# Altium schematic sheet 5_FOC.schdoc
size 431 x 309 mm
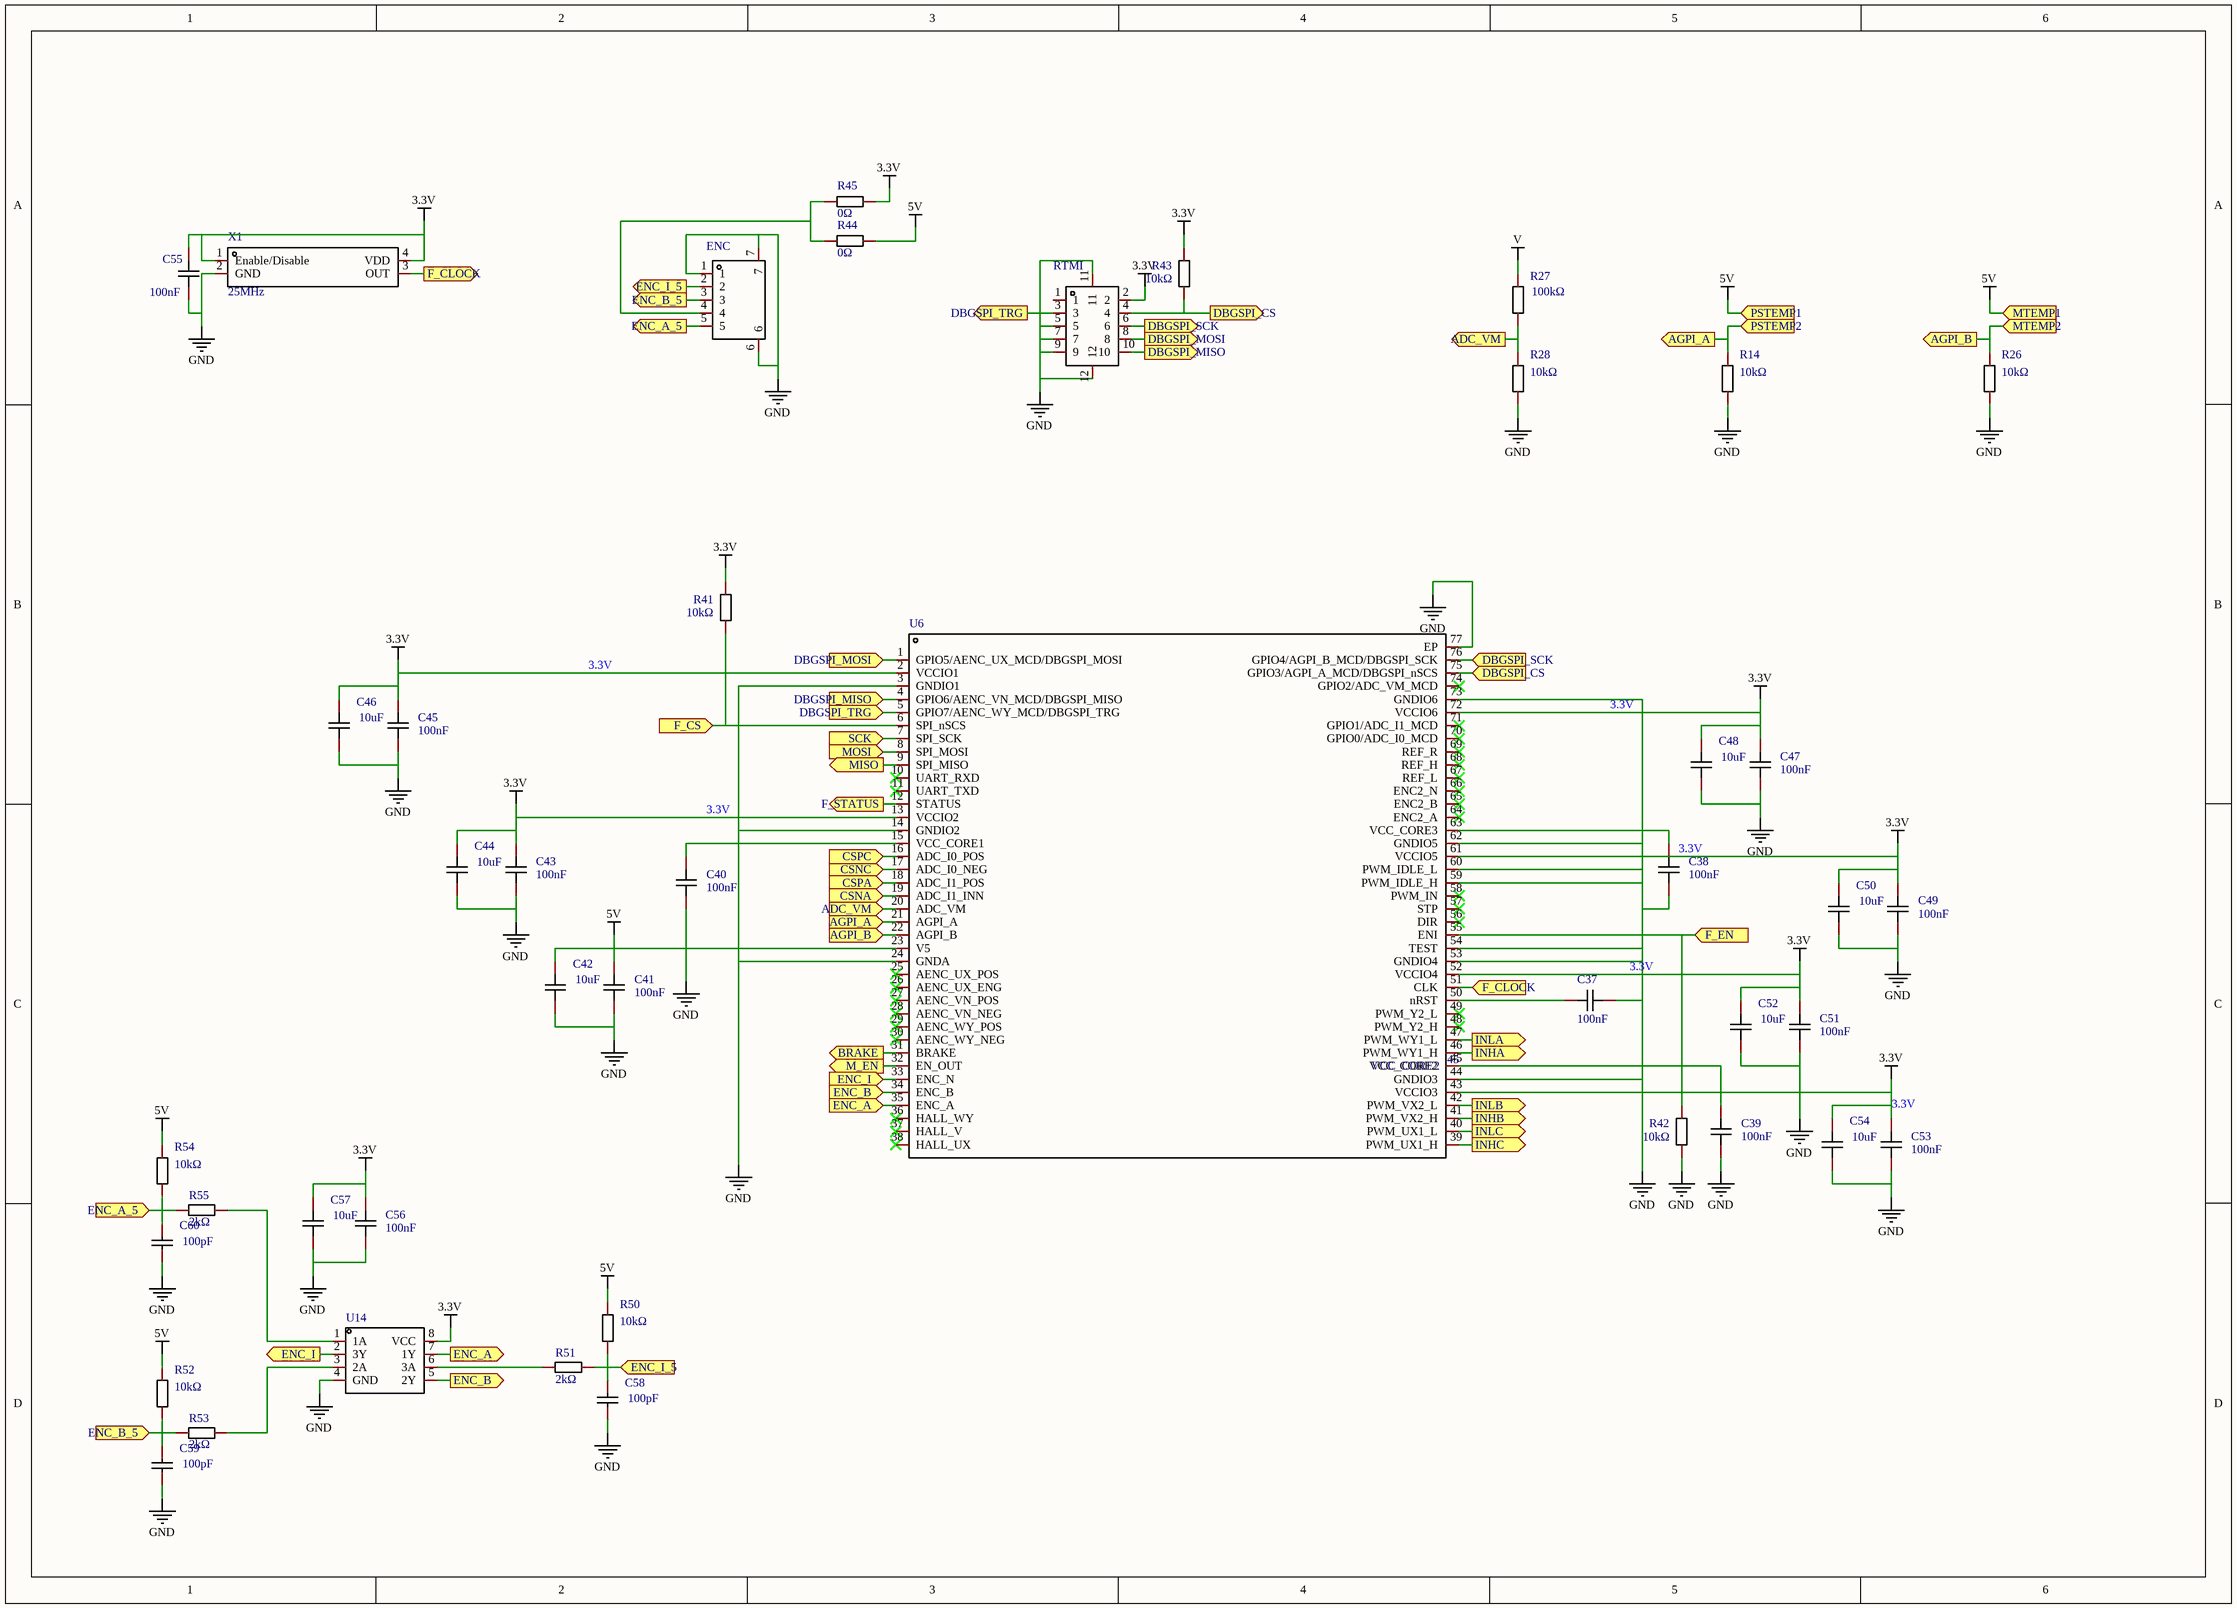
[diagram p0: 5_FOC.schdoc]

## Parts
C37  value 100nF  [C0402]  (hidden comment: CC0402KRX7R7BB104)
C38  value 100nF  [C0402]  (hidden comment: CC0402KRX7R7BB104)
C39  value 100nF  [C0402]  (hidden comment: CC0402KRX7R7BB104)
C40  value 100nF  [C0402]  (hidden comment: CC0402KRX7R7BB104)
C41  value 100nF  [C0402]  (hidden comment: CC0402KRX7R7BB104)
C42  value 10uF  [C0402]  (hidden comment: CL05A106MP5NUNC)
C43  value 100nF  [C0402]  (hidden comment: CC0402KRX7R7BB104)
C44  value 10uF  [C0402]  (hidden comment: CL05A106MP5NUNC)
C45  value 100nF  [C0402]  (hidden comment: CC0402KRX7R7BB104)
C46  value 10uF  [C0402]  (hidden comment: CL05A106MP5NUNC)
C47  value 100nF  [C0402]  (hidden comment: CC0402KRX7R7BB104)
C48  value 10uF  [C0402]  (hidden comment: CL05A106MP5NUNC)
C49  value 100nF  [C0402]  (hidden comment: CC0402KRX7R7BB104)
C50  value 10uF  [C0402]  (hidden comment: CL05A106MP5NUNC)
C51  value 100nF  [C0402]  (hidden comment: CC0402KRX7R7BB104)
C52  value 10uF  [C0402]  (hidden comment: CL05A106MP5NUNC)
C53  value 100nF  [C0402]  (hidden comment: CC0402KRX7R7BB104)
C54  value 10uF  [C0402]  (hidden comment: CL05A106MP5NUNC)
C55  value 100nF  [C0402]  (hidden comment: CC0402KRX7R7BB104)
C56  value 100nF  [C0402]  (hidden comment: CC0402KRX7R7BB104)
C57  value 10uF  [C0402]  (hidden comment: CL05A106MP5NUNC)
C58  value 100pF  [C0402]  (hidden comment: CC0402JRNPO9BN101)
C59  value 100pF  [C0402]  (hidden comment: CC0402JRNPO9BN101)
C60  value 100pF  [C0402]  (hidden comment: CC0402JRNPO9BN101)
ENC  A1002WR-S-5P  [CONN-SMD_A1002WR-S-5P]  (value not drawn)
R14  value 10kΩ  [R0402]  (hidden comment: 0402WGF1002TCE)
R26  value 10kΩ  [R0402]  (hidden comment: 0402WGF1002TCE)
R27  value 100kΩ  [R0402]  (hidden comment: PTFR0402B100KN9)
R28  value 10kΩ  [R0402]  (hidden comment: 0402WGF1002TCE)
R41  value 10kΩ  [R0402]  (hidden comment: 0402WGF1002TCE)
R42  value 10kΩ  [R0402]  (hidden comment: 0402WGF1002TCE)
R43  value 10kΩ  [R0402]  (hidden comment: 0402WGF1002TCE)
R44  value 0Ω  [R0402]  (hidden comment: RC0402FR-070RL)
R45  value 0Ω  [R0402]  (hidden comment: RC0402FR-070RL)
R50  value 10kΩ  [R0402]  (hidden comment: 0402WGF1002TCE)
R51  value 2kΩ  [R0402]  (hidden comment: AR02BTC2001)
R52  value 10kΩ  [R0402]  (hidden comment: 0402WGF1002TCE)
R53  value 2kΩ  [R0402]  (hidden comment: AR02BTC2001)
R54  value 10kΩ  [R0402]  (hidden comment: 0402WGF1002TCE)
R55  value 2kΩ  [R0402]  (hidden comment: AR02BTC2001)
RTMI  DF20F-10DP-1H(59)  [CONN-SMD_DF20F-10DP-1H-59]  (value not drawn)
U6  NAME: VCC_CORE2  NUMBER: 45  [QFN-76_L10.5-W6.5-P0.40-TL-EP]  (hidden comment: TMC4671-LA)
U14  SN74LVC3G17DCUR  [VSSOP-8_L2.4-W2.1-P0.50-LS3.2-BL]  (value not drawn)
X1  value 25MHz  [OSC-SMD_4P-L3.2-W2.5-BL]  (hidden comment: OT322525MJBA4SL)

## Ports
ADC_VM (in), ADC_VM (out), AGPI_A (in), AGPI_A (out), AGPI_B (in), AGPI_B (out), BRAKE (out), CSNA (in), CSNC (in), CSPA (in), CSPC (in), DBGSPI_CS (in), DBGSPI_CS (out), DBGSPI_MISO (in), DBGSPI_MISO (out), DBGSPI_MOSI (in), DBGSPI_MOSI (out), DBGSPI_SCK (in), DBGSPI_SCK (out), DBGSPI_TRG (in), DBGSPI_TRG (out), ENC_A (in), ENC_A (out), ENC_A_5 (in), ENC_A_5 (out), ENC_B (in), ENC_B (out), ENC_B_5 (in), ENC_B_5 (out), ENC_I (in), ENC_I (out), ENC_I_5 (in), ENC_I_5 (out), F_CLOCK (in), F_CLOCK (out), F_CS (in), F_EN (in), F_STATUS (out), INHA (out), INHB (out), INHC (out), INLA (out), INLB (out), INLC (out), M_EN (out), MISO (out), MOSI (in), MTEMP1 (in), MTEMP2 (in), PSTEMP1 (in), PSTEMP2 (in), SCK (in)

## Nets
3.3V: C43.1 C44.2 C45.1 C46.2 C47.1 C48.2 C49.1 C50.2 C51.1 C52.2 C53.1 C54.2 C55.2 C56.1 C57.2 R41.2 R43.2 R45.2 RTMI.2 U6.2(VCCIO1) U6.13(VCCIO2) U6.43(VCCIO3) U6.52(VCCIO4) U6.61(VCCIO5) U6.72(VCCIO6) U14.8(VCC) X1.1(Enable/Disable) X1.4(VDD)
5V: C41.1 C42.2 R44.2 R50.2 R52.2 R54.2 U6.23(V5) ; port PSTEMP1, port MTEMP1
GND: C37.1 C38.1 C39.2 C40.2 C41.2 C42.1 C43.2 C44.1 C45.2 C46.1 C47.2 C48.1 C49.2 C50.1 C51.2 C52.1 C53.2 C54.1 C55.1 C56.2 C57.1 C58.1 C59.1 C60.1 ENC.1 ENC.6 ENC.7 R14.1 R26.1 R28.1 R42.1 RTMI.5 RTMI.7 RTMI.9 RTMI.11 RTMI.12 U6.3(GNDIO1) U6.14(GNDIO2) U6.24(GNDA) U6.44(GNDIO3) U6.53(GNDIO4) U6.54(TEST) U6.59(PWM_IDLE_H) U6.60(PWM_IDLE_L) U6.62(GNDIO5) U6.73(GNDIO6) U6.77(EP) U14.4(GND) X1.2(GND)
V: R27.2
ADC_VM: R27.1 R28.2 U6.20(ADC_VM) ; port ADC_VM
AGPI_A: R14.2 U6.21(AGPI_A) ; port PSTEMP2, port AGPI_A
AGPI_B: R26.2 U6.22(AGPI_B) ; port MTEMP2, port AGPI_B
BRAKE: U6.31(BRAKE) ; port BRAKE
CSNA: U6.19(ADC_I1_INN) ; port CSNA
CSNC: U6.17(ADC_I0_NEG) ; port CSNC
CSPA: U6.18(ADC_I1_POS) ; port CSPA
CSPC: U6.16(ADC_I0_POS) ; port CSPC
DBGSPI_CS: R43.1 RTMI.4 U6.75(GPIO3/AGPI_A_MCD/DBGSPI_nSCS) ; port DBGSPI_CS
DBGSPI_MISO: RTMI.10 U6.4(GPIO6/AENC_VN_MCD/DBGSPI_MISO) ; port DBGSPI_MISO
DBGSPI_MOSI: RTMI.8 U6.1(GPIO5/AENC_UX_MCD/DBGSPI_MOSI) ; port DBGSPI_MOSI
DBGSPI_SCK: RTMI.6 U6.76(GPIO4/AGPI_B_MCD/DBGSPI_SCK) ; port DBGSPI_SCK
DBGSPI_TRG: RTMI.3 U6.5(GPIO7/AENC_WY_MCD/DBGSPI_TRG) ; port DBGSPI_TRG
ENC_A: U6.35(ENC_A) U14.7(1Y) ; port ENC_A
ENC_A_5: C60.2 ENC.5 R54.1 R55.2 ; port ENC_A_5
ENC_B: U6.34(ENC_B) U14.5(2Y) ; port ENC_B
ENC_B_5: C59.2 ENC.3 R52.1 R53.2 ; port ENC_B_5
ENC_I: U6.33(ENC_N) U14.2(3Y) ; port ENC_I
ENC_I_5: C58.2 ENC.2 R50.1 R51.1 ; port ENC_I_5
F_CLOCK: U6.51(CLK) X1.3(OUT) ; port F_CLOCK
F_CS: R41.1 U6.6(SPI_nSCS) ; port F_CS
F_EN: R42.2 U6.55(ENI) ; port F_EN
F_STATUS: U6.12(STATUS) ; port F_STATUS
INHA: U6.46(PWM_WY1_H) ; port INHA
INHB: U6.41(PWM_VX2_H) ; port INHB
INHC: U6.39(PWM_UX1_H) ; port INHC
INLA: U6.47(PWM_WY1_L) ; port INLA
INLB: U6.42(PWM_VX2_L) ; port INLB
INLC: U6.40(PWM_UX1_L) ; port INLC
M_EN: U6.32(EN_OUT) ; port M_EN
MISO: U6.9(SPI_MISO) ; port MISO
MOSI: U6.8(SPI_MOSI) ; port MOSI
SCK: U6.7(SPI_SCK) ; port SCK
NetC37_2: C37.2 U6.50(nRST)
NetC38_2: C38.2 U6.63(VCC_CORE3)
NetC39_1: C39.1 U6.45(VCC_CORE2)
NetC40_1: C40.1 U6.15(VCC_CORE1)
NetENC_4: ENC.4 R44.1 R45.1
NetR51_2: R51.2 U14.6(3A)
NetR53_1: R53.1 U14.3(2A)
NetR55_1: R55.1 U14.1(1A)

Not connected (* = marked no-connect by the designer): RTMI 1; U6 10(UART_RXD)* 11(UART_TXD)* 25(AENC_UX_POS)* 26(AENC_UX_ENG)* 27(AENC_VN_POS)* 28(AENC_VN_NEG)* 29(AENC_WY_POS)* 30(AENC_WY_NEG)* 36(HALL_WY)* 37(HALL_V)* 38(HALL_UX)* 48(PWM_Y2_H)* 49(PWM_Y2_L)* 56(DIR)* 57(STP)* 58(PWM_IN)* 64(ENC2_A)* 65(ENC2_B)* 66(ENC2_N)* 67(REF_L)* 68(REF_H)* 69(REF_R)* 70(GPIO0/ADC_I0_MCD)* 71(GPIO1/ADC_I1_MCD)* 74(GPIO2/ADC_VM_MCD)*

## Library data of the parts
C37-C41 C43 C45 C47 C49 C51 C53 C55 C56 = CC0402KRX7R7BB104: Capacitance:100nF Tolerance:±10% Tolerance:±10% Voltage Rated:16V Temperature Coefficient:X7R; Manufacturer: YAGEO(国巨); Add into BOM: yes; Tolerance: ±10%; Voltage Rated: 16V; Temperature Coefficient: X7R
C42 C44 C46 C48 C50 C52 C54 C57 = CL05A106MP5NUNC: Capacitance:10uF Tolerance:±20% Tolerance:±20% Voltage Rated:10V Temperature Coefficient:X5R; Manufacturer: SAMSUNG(三星); Symbol: CL05A106MP5NUNC_C315248; Add into BOM: yes; Tolerance: ±20%; Voltage Rated: 10V; Temperature Coefficient: X5R
C58-C60 = CC0402JRNPO9BN101: Capacitance:100pF Tolerance:±5% Tolerance:±5% Voltage Rated:50V Temperature Coefficient:NP0; Manufacturer: YAGEO(国巨); Add into BOM: yes; Tolerance: ±5%; Voltage Rated: 50V; Temperature Coefficient: NP0
ENC = A1002WR-S-5P: Reference Series:SH Pitch:1mm Pins Structure:1x5P Number of Rows:1 Number of PINs Per Row:5 Row Spacing:- Mounting Style:- Contact Material:磷青铜; Manufacturer: CJT(长江连接器); Add into BOM: yes; Reference Series: SH; Pitch: 1mm; Pins Structure: 1x5P; Number of PINs Per Row: 5
R14 R26 R28 R41-R43 R50 R52 R54 = 0402WGF1002TCE: Type:厚膜电阻 Resistance:10kΩ Tolerance:±1% Tolerance:±1% Power(Watts):1/16W Temperature Coefficient:±100ppm/ Temperature Coefficient:±100ppm/ Overload Voltage (Max):50V Operating Temperature Range:-55~+155 Operating Temperature Range:-55~+155; Manufacturer: UNI-ROYAL(厚声); Add into BOM: yes; Tolerance: ±1%; Power(Watts): 1/16W; Overload Voltage (Max): 50V
R27 = PTFR0402B100KN9: Type:薄膜电阻 Resistance:100kΩ Tolerance:±0.1% Power(Watts):60mW Temperature Coefficient:±10ppm/ Temperature Coefficient:±10ppm/ Overload Voltage (Max):75V Operating Temperature Range:-55~+125 Operating Temperature Range:-55~+125; Manufacturer: RESI(开步睿思）; Add into BOM: yes; Tolerance: ±0.1%; Power(Watts): 60mW; Temperature Coefficient: ±10ppm/; Overload Voltage (Max): 75V
R44 = RC0402FR-070RL: Temperature Coefficient:- Temperature Coefficient:- Power(Watts):1/16W Tolerance:±1% Resistance:0Ω Overload Voltage (Max):50V Operating Temperature Range:-55~+155 Operating Temperature Range:-55~+155; Manufacturer: YAGEO(国巨); Add into BOM: yes; Power(Watts): 1/16W; Tolerance: ±1%; Overload Voltage (Max): 50V
R45 = RC0402FR-070RL: Temperature Coefficient:- Temperature Coefficient:- Power(Watts):1/16W Tolerance:±1% Resistance:0Ω Overload Voltage (Max):50V Operating Temperature Range:-55~+155 Operating Temperature Range:-55~+155; Manufacturer: YAGEO(国巨); Add into BOM: no; Convert to PCB: yes; Power(Watts): 1/16W; Tolerance: ±1%; Overload Voltage (Max): 50V
R51 R53 R55 = AR02BTC2001: Type:薄膜电阻 Resistance:2kΩ Tolerance:±0.1% Power(Watts):1/16W Temperature Coefficient:±25ppm/ Temperature Coefficient:±25ppm/ Overload Voltage (Max):25V Operating Temperature Range:-55~+155 Operating Temperature Range:-55~+155; Manufacturer: 光颉(Viking); Add into BOM: yes; Tolerance: ±0.1%; Power(Watts): 1/16W; Temperature Coefficient: ±25ppm/; Overload Voltage (Max): 25V
RTMI = DF20F-10DP-1H(59): Reference Series:- Pitch:1mm Pins Structure:2x5P Number of Rows:2 Number of PINs Per Row:5 Row Spacing:- Gender:公型插针 Mounting Style:卧贴 Current Rating (Max):- Operating Temperature Range:- Operating Temperature Range:-; Manufacturer: HRS(广濑); Add into BOM: yes; Pitch: 1mm; Pins Structure: 2x5P; Number of PINs Per Row: 5; Gender: 公型插针
U6 = TMC4671-LA: Manufacturer: TRINAMIC; Symbol: TMC4671-ES; Add into BOM: yes
U14 = SN74LVC3G17DCUR: Series:74LVC Logic Type:缓冲器，非反向 Number of Elements:3 Number of Bits per Element:1 Input Type:施密特触发器 Output Type:推挽式 Current - Output High, Low:32mA、32mA Voltage - Supply:1.65V ~ 5.5V Operating Temperature:-40~+125（TA）; Manufacturer: TI(德州仪器); Add into BOM: yes; Number of Elements: 3; Number of Bits per Element: 1; Input Type: 施密特触发器; Output Type: 推挽式
X1 = OT322525MJBA4SL: Voltage - Supply:1.8V~3.3V Current - Supply (Max):5mA Frequency:25MHz Frequency Stability:10ppm Operating Temperature:-40~85; Manufacturer: YXC扬兴科技; Add into BOM: yes; Current - Supply (Max): 5mA; Frequency Stability: 10ppm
